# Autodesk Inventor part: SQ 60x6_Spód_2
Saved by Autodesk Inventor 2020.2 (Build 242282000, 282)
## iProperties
Created: 2006-08
Part Number: SQ 60x6_Spód_2
Material: Ogólny
Document SubType Name: Modeling
Designer: F.Stasiak
Manufacturer: Standard
Standards Organization: Custom
Stock Number: DIN EN 10210-2 SQ 60x6
Density: 1 g/cm^3
Appearance: Domyślna
Manager: www.cadconsulting.pl
Company: Fabian Stasiak CAD Consulting
G_L: 1000,0 mm
G_W: 60,000 mm
G_H: 60,000 mm
AFG_Item: 60 x 60 x 6
Author: F.Stasiak
Subject: Zbiór ćwiczeń. Autodesk Inventor 2020. Kurs podstawowy
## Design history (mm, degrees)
sketch "AFG_Detailed"
  geometry: L1 (-12, 54)-(-48, 54); L2 (-54, 48)-(-54, 12); L3 (-48, 6)-(-12, 6); L4 (-6, 12)-(-6, 48); L5 (-12, 60)-(-48, 60); L6 (-60, 48)-(-60, 12); L7 (-48, 0)-(-12, 0); L8 (0, 12)-(0, 48); A1 r 6 centre (-12, 48) between (-6, 48) and (-12, 54); A2 r 12 centre (-12, 48) between (0, 48) and (-12, 60); A3 r 6 centre (-12, 12) between (-12, 6) and (-6, 12); A4 r 12 centre (-12, 12) between (-12, 0) and (0, 12); A5 r 12 centre (-48, 12) between (-60, 12) and (-48, 0); A6 r 6 centre (-48, 12) between (-54, 12) and (-48, 6); A7 r 6 centre (-48, 48) between (-48, 54) and (-54, 48); A8 r 12 centre (-48, 48) between (-48, 60) and (-60, 48); 4 further points
  constraints: 16 end point, 16 point on circle, 16 tangent, 8 centre point, 6 point on line, 4 parallel, 2 perpendicular, 1 vertical
  dimensions: "d15" = 60 distance of point (-60, 0) point (0, 0) (= GEO_B); "d16" = 6 distance between parallel lines of L7 L3 (= GEO_S); "d17" = 6 distance between parallel lines of L8 L4 (= GEO_S); "d18" = 6 distance between parallel lines of L5 L1 (= GEO_S); "d19" = 6 distance between parallel lines of L6 L2 (= GEO_S); "d20" = 30 distance from line of point (-30, 30) L7 (= 0.5 x GEO_H); "d30" = 6 radius of A1 (= GEO_R1 - GEO_S); "GEO_R1" = 12 radius of A2; "d32" = 6 radius of A3 (= GEO_R1 - GEO_S); "d33" = 12 radius of A4 (= GEO_R1); "d34" = 12 radius of A5 (= GEO_R1); "d35" = 6 radius of A6 (= GEO_R1 - GEO_S); "d36" = 6 radius of A7 (= GEO_R1 - GEO_S); "d37" = 12 radius of A8 (= GEO_R1); "d38" = 30 distance from line of L6 point (-30, 30) (= 0.5 x GEO_B); "d39" = 60 distance between parallel lines of L7 L5 (= GEO_H)
sketch "AFG_Medium"
  geometry: L1 (-6, 54)-(-54, 54); L2 (-54, 54)-(-54, 6); L3 (-54, 6)-(-6, 6); L4 (-6, 6)-(-6, 54); L5 (0, 60)-(-60, 60); L6 (-60, 60)-(-60, 0); L7 (-60, 0)-(0, 0); L8 (0, 0)-(0, 60); 1 further point
  constraints: 16 end point, 4 parallel, 2 perpendicular, 1 vertical
  dimensions: "GEO_B" = 60 distance of L6.end L7.end; "GEO_S" = 6 distance between parallel lines of L7 L3; "d5" = 6 distance between parallel lines of L8 L4 (= GEO_S); "d6" = 6 distance between parallel lines of L5 L1 (= GEO_S); "d7" = 6 distance between parallel lines of L6 L2 (= GEO_S); "d12" = 30 distance from line of point (-30, 30) L7 (= 0.5 x GEO_H); "d40" = 60 distance between parallel lines of L7 L5 (= GEO_H); "d41" = 30 distance from line of L6 point (-30, 30) (= 0.5 x GEO_B)
sketch "AFG_Simplified"
  geometry: L1 (0, 60)-(-60, 60); L2 (-60, 60)-(-60, 0); L3 (-60, 0)-(0, 0); L4 (0, 0)-(0, 60); 1 further point
  constraints: 8 end point, 2 parallel, 1 perpendicular, 1 vertical
  dimensions: "d23" = 60 distance of L2.end L3.end (= GEO_B); "d28" = 30 distance from line of point (-30, 30) L3 (= 0.5 x GEO_H); "d42" = 60 distance between parallel lines of L3 L1 (= GEO_H); "d43" = 30 distance from line of point (-30, 30) L2 (= 0.5 x GEO_B)
derived "Szkielet podstawy.ipt"
  sketch "Szkic1"
    geometry: L1 (0, 0)-(1500, 0) reference; L2 (1500, 0)-(1500, 1000) reference; L3 (1500, 1000)-(0, 1000) reference; L4 (0, 1000)-(0, 0) reference
  sketch "Szkic2"
    geometry: L1 (0, 1000)-(0, 0) reference; L2 (0, 0)-(1500, 0) reference; L3 (1500, 0)-(1500, 1000) reference; L4 (500, 1000)-(1500, 1000) reference; L5 (1500, 1000)-(1500, 0) reference; L6 (1500, 0)-(500, 0) reference; L7 (500, 0)-(500, 1000) reference; L8 (1500, 1000)-(0, 1000) reference
node "AFG_StartWorkPoint_SQ 60x6_Spód_2"
node "AFG_EndWorkPoint_SQ 60x6_Spód_2"
node "AFG_HelpAxis"
node "AFG_HelpStart"
node "AFG_HelpEnd"
node "AFG_Midplane"
  node "AFG_Startplane"
  node "AFG_EndPlane"
node "AFG_Profile_AxisX_for_External_Matrix"
extrude "AFG_Detailed_SQ 60x6_Spód_2" join sketch "AFG_Detailed" stored distance "d49" = 0.13; taper "d50" = 0 deg
extrude "AFG_Simplified_SQ 60x6_Spód_2" join sketch "AFG_Simplified" stored distance "d51" = 0.13; taper "d52" = 0 deg
node "AFG_StartWorkPoint_SQ 60x6_Spód_3"
node "AFG_EndWorkPoint_SQ 60x6_Spód_3"
node "AFG_ENDCUTPLANE_SQ 60x6_Spód_2"
node "AFG_StartWorkPoint_SQ 60x6_Spód_1"
node "AFG_EndWorkPoint_SQ 60x6_Spód_1"
node "AFG_STARTCUTPLANE_SQ 60x6_Spód_2"
node "Bryła1"
node "Korpusy bryłowe"
node "Korpusy powierzchniowe"
other parameters: "GEO_H" = 60, "AFG_Origin_X" = 0 (= 0 x GEO_B) [user parameter], "AFG_Origin_Y" = 0 (= 0 x GEO_H) [user parameter], "AFG_IP_X2" = 0 (= 0 x GEO_B) [user parameter], "AFG_IP_Y4" = 0 (= 0 x GEO_H) [user parameter], "AFG_IP_X6" = 0 (= 0 x GEO_B) [user parameter], "AFG_IP_Y8" = 0 (= 0 x GEO_H) [user parameter], "d47" = 0, "d48" = 0, "G_L" = 1000 [user parameter], "d55" = 0, "d58" = 0
